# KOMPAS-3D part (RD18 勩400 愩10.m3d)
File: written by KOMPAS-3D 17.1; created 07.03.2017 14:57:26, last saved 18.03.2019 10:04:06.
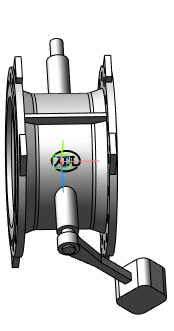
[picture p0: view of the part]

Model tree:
1. Операция без истории:2  (labels: Сталь 20  ГОСТ 1050-88)

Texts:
  RD18 Ду100 Ру16
  RD18 Ду150 Ру16
  RD18 Ду200 Ру16
  RD18 Ду250 Ру16
  RD18 Ду300 Ру16
  RD18 Ду350 Ру16
  RD18 Ду400 Ру10
  RD18 Ду400 Ру16
  RD18 Ду450 Ру10
  RD18 Ду450 Ру16
  RD18 Ду500 Ру10
  RD18 Ду500 Ру16
  RD18 Ду600 Ру10
  RD18 Ду600 Ру16
  RD18 Ду700 Ру10
  RD18 Ду700 Ру16
  RD18 Ду800 Ру10
  RD18 Ду800 Ру16
  RD18 Ду900 Ру10
  RD18 Ду900 Ру16
  RD18 Ду1000 Ру10
  RD18 Ду1000 Ру16
  RD18 Ду1200 Ру16
  RD18 Ду1400 Ру16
